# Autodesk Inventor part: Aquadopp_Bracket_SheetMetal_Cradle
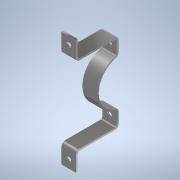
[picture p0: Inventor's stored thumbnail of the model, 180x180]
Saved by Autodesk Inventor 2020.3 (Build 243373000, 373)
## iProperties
Created: 2020-09
Part Number: Aquadopp_Bracket_SheetMetal_Cradle
Material: Stainless Steel
Document SubType Name: Sheet Metal
Designer: biggshj
Manufacturer: Standard
Standards Organization: Custom
Density: 8 g/cm^3
Sheet Metal Rule: Default_mm
Appearance: Semi-Polished
Mass: 212.018 g
Surface Area: 202.907 cm^2
Volume: 26.5023 cm^3
Author: biggshj
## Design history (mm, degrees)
node "Contour Flange1"
  sketch "Sketch2"
    geometry: L1 (0, 38.678)-(0, 68.678); L2 (0, 68.678)-(-70, 68.678); L3 (-70, 68.678)-(-70, 98.678); L4 (0, -38.678)-(0, -68.678); L5 (0, -68.678)-(-70, -68.678); L6 (-70, -68.678)-(-70, -98.678); L7 (0, 0)-(5, 0); L8 (0, -138.149)-(0, 138.149) reference; A1 r 39 centre (5, 0) between (0, 38.678) and (0, -38.678)
    constraints: 14 end point, 4 perpendicular, 2 collinear, 2 point on circle, 2 vertical, 1 centre point, 1 coincident, 1 horizontal
    dimensions: "d0" = 5 distance of L7.start L7.end; "d1" = 39 radius of A1; "d2" = 30 distance of L4.start L4.end; "d3" = 70 distance of L4.end L5.end; "d4" = 30 distance of L5.end L6.end; "d5" = 30 distance of L1.start L1.end; "d6" = 70 distance of L1.end L2.end; "d7" = 30 distance of L2.end L3.end
sketch "Sketch3"
  geometry: L1 (0, 0)-(0, 13.5); L2 (0, 27)-(0, 0) reference; L3 (0, 98.678)-(0, 13.678); L4 (0, 27)-(0, 0) reference; L5 (12.5, 13.678)-(0, 13.678); C1 r 4.025 at (12.5, 13.678)
  constraints: 6 end point, 1 centre point, 1 midpoint, 1 point on line
  dimensions: "d21" = 8.05 diameter of C1; "d32" = 90 deg angle of L2 L5; "d33" = 12.5 distance of L5.start L3.end; "d34" = 85 distance of L3.start L3.end
extrude "Extrusion1" cut sketch "Sketch3" distance "d23" = 10; taper "d24" = 0 deg
mirror "Mirror1"
sketch "Sketch4"
  geometry: L1 (0, 62.678)-(0, 9.678); L2 (0, 9.678)-(12.5, 9.678); C1 r 4.025 at (12.5, 9.678)
  constraints: 4 end point, 1 centre point, 1 coincident, 1 horizontal, 1 vertical
  dimensions: "d25" = 53 distance of L1.start L1.end; "d26" = 12.5 distance of L1.end L2.end; "d28" = 8.05 diameter of C1
extrude "Extrusion2" cut sketch "Sketch4" distance "d30" = 10; taper "d31" = 0 deg
mirror "Mirror2"
body "Solid1"
face "Plate1" dims "d8" = 3 (= Thickness), "d9" = 3 (= BendReliefWidth), "d10" = 1.5 (= BendReliefDepth), "d11" = 6 (= MinimumRemnant), "d12" = 3 (= TransitionRadius), "d13" = 25, "d14" = 3 (= BendRadius), "d15" = 3.048, "d16" = 12 (= CornerReliefSize), "d17" = 3 (= GapSize), "d18" = 3 (= JacobiRadiusSize), "SeamGap" = 0.01
bend "Bend1" dims "d8" = 3 (= Thickness), "d9" = 3 (= BendReliefWidth), "d10" = 1.5 (= BendReliefDepth), "d11" = 6 (= MinimumRemnant), "d12" = 3 (= TransitionRadius), "d14" = 3 (= BendRadius), "d15" = 3.048, "SeamGap" = 0.01
feature "Corner1" dims "d15" = 3.048, "d16" = 12 (= CornerReliefSize), "d17" = 3 (= GapSize), "d18" = 3 (= JacobiRadiusSize)
other parameters: "Thickness" = 3 (derived), "BendRadius" = 3 (= Thickness), "BendReliefWidth" = 3 (= Thickness), "BendReliefDepth" = 1.5 (= 0.5 x Thickness), "CornerReliefSize" = 12 (= 4 x Thickness), "MinimumRemnant" = 6 (= 2 x Thickness), "TransitionRadius" = 3 (= BendRadius), "JacobiRadiusSize" = 3 (= BendRadius), "GapSize" = 3 (= Thickness)
